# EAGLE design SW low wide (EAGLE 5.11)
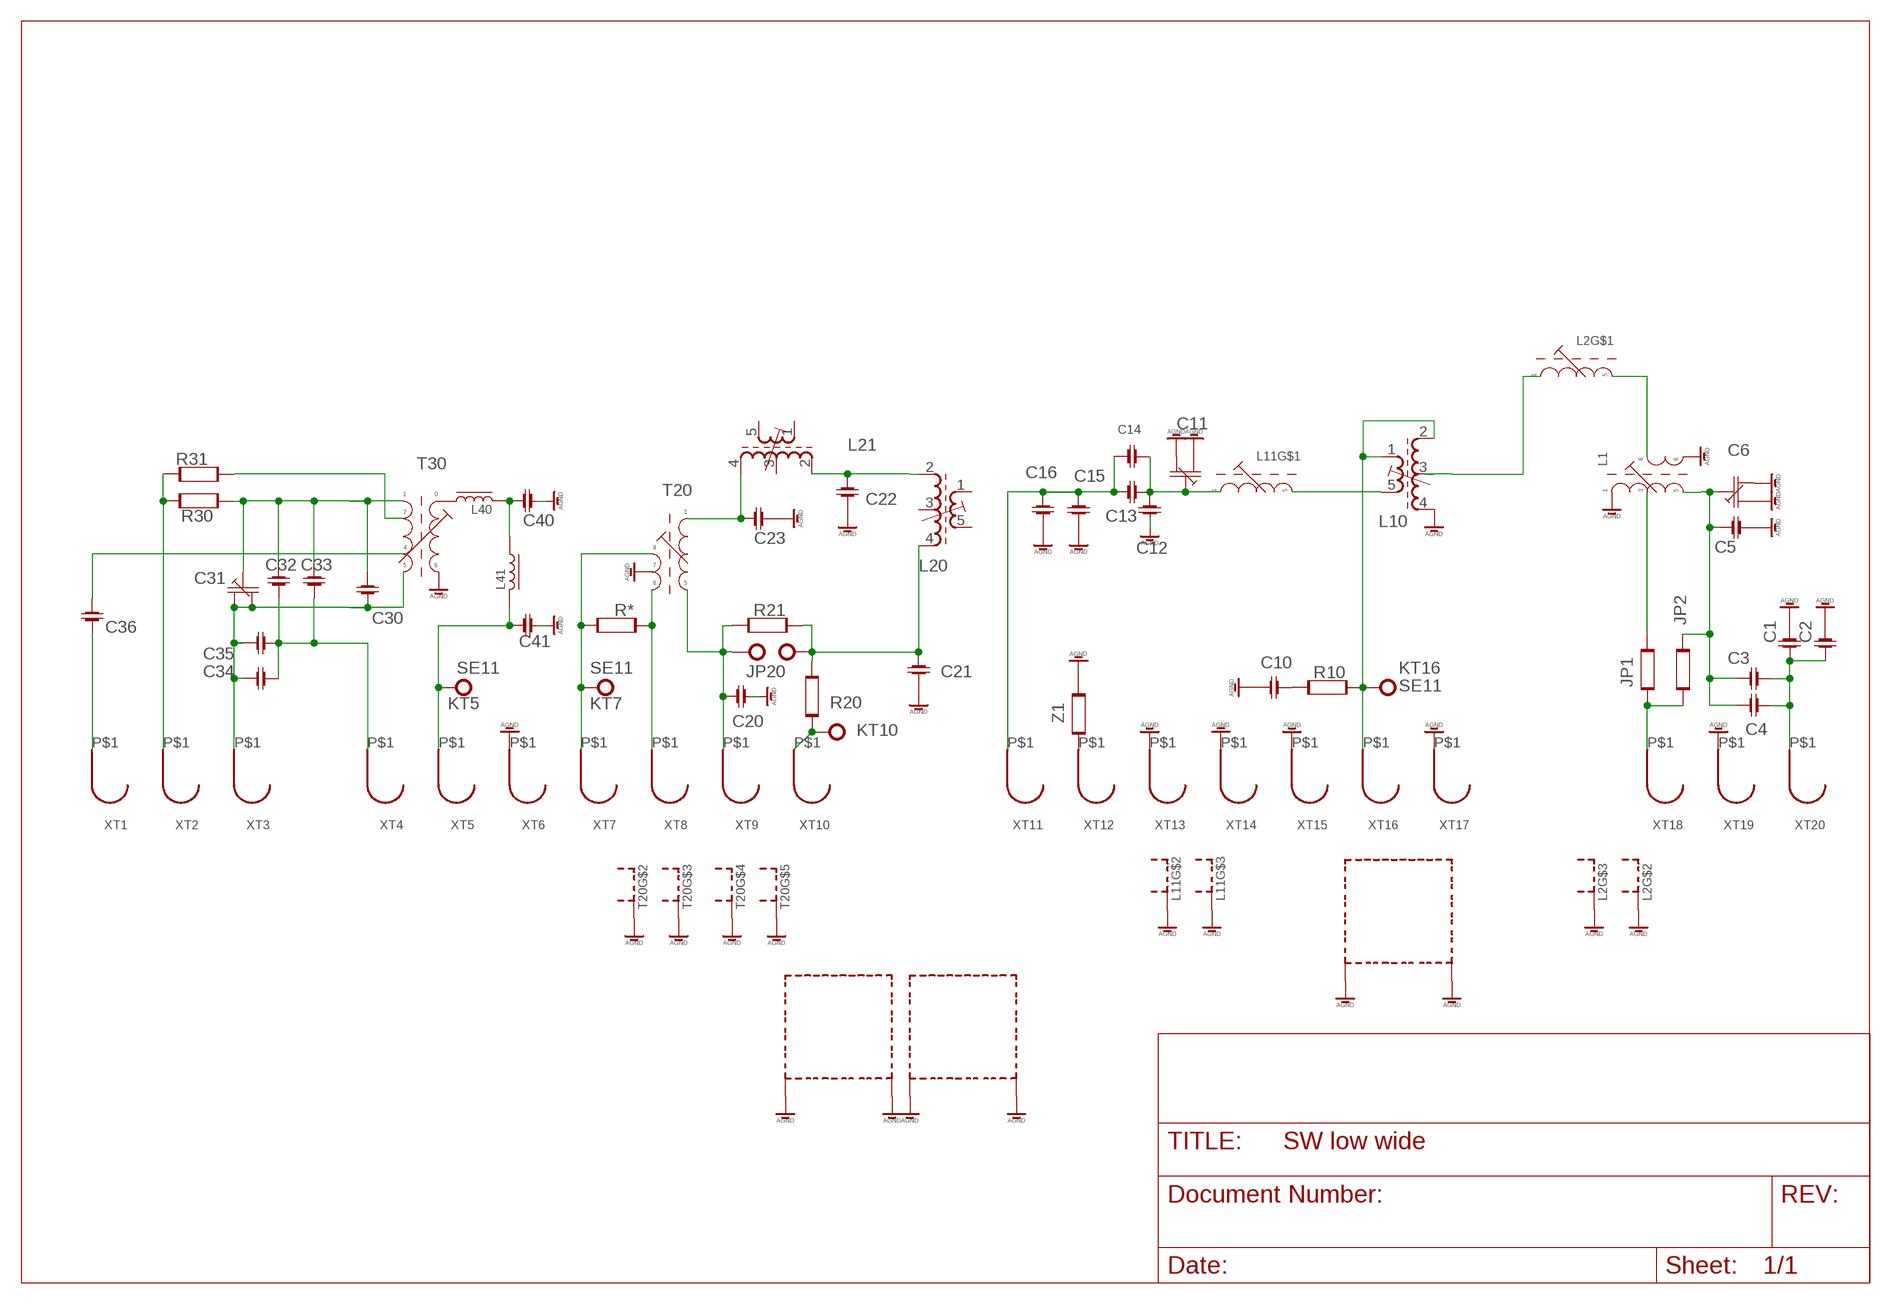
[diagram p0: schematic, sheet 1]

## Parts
C1  C-1206-0805  [RC-SMD-UNIV]
C2  C-1206-0805  [RC-SMD-UNIV]
C3  C-1206-0805  [RC-SMD-UNIV]
C4  C-1206-0805  [RC-SMD-UNIV]
C5  C-1206-0805  [RC-SMD-UNIV]
C6  C-TRIM-AM  [C-TRIM-ORIG]
C10  C-1206-0805  [RC-SMD-UNIV]
C11  C-TRIM-AM  [C-TRIM-ORIG]
C12  C-1206-0805  [RC-SMD-UNIV]
C13  C-1206-0805  [RC-SMD-UNIV]
C14  C-1206-0805  [RC-SMD-UNIV]
C15  C-1206-0805  [RC-SMD-UNIV]
C16  C-1206-0805  [RC-SMD-UNIV]
C20  C-1206-0805  [RC-SMD-UNIV]
C21  C-1206-0805  [RC-SMD-UNIV]
C22  C-1206-0805  [RC-SMD-UNIV]
C23  C-1206-0805  [RC-SMD-UNIV]
C30  C-1206-0805  [RC-SMD-UNIV]
C31  C-TRIM-AM  [C-TRIM-ORIG]
C32  C-1206-0805  [RC-SMD-UNIV]
C33  C-1206-0805  [RC-SMD-UNIV]
C34  C-1206-0805  [RC-SMD-UNIV]
C35  C-1206-0805  [RC-SMD-UNIV]
C36  C-1206-0805  [RC-SMD-UNIV]
C40  C-1206-0805  [RC-SMD-UNIV]
C41  C-1206-0805  [RC-SMD-UNIV]
JP1  R-1206-0805  [RC-SMD-UNIV]
JP2  R-1206-0805  [RC-SMD-UNIV]
JP20  SE11  [SE11]
KT1  SE11  [SE11]
KT5  SE11  [SE11]
KT7  SE11  [SE11]
KT10  SE11  [SE11]
KT16  SE11  [SE11]
L1  L-MOD-SW-IN-OPEN  [L-KW-LARGE]
L2  L-MOD-SW-GAP  [L-7-MM]
L10  71-5-24153  [71-5]
L11  L-MOD-SW-GAP  [L-7-MM]
L20  71-5-24153  [71-5]
L21  71-5-24153  [71-5]
L40  L-US0207/10  [0207/10]
L41  L-US0207/10  [0207/10]
R10  R-1206-0805  [RC-SMD-UNIV]
R20  R-1206-0805  [RC-SMD-UNIV]
R21  R-1206-0805  [RC-SMD-UNIV]
R30  R-1206-0805  [RC-SMD-UNIV]
R31  R-1206-0805  [RC-SMD-UNIV]
R*  R-1206-0805  [RC-SMD-UNIV]
T20  209-N-T90  [L-10-7-MM]
T30  L-MOD-OSC-SW  [L-KW-LARGE]
XT1  CONTACT-RF  [CONTACT-RF]
XT2  CONTACT-RF  [CONTACT-RF]
XT3  CONTACT-RF  [CONTACT-RF]
XT4  CONTACT-RF  [CONTACT-RF]
XT5  CONTACT-RF  [CONTACT-RF]
XT6  CONTACT-RF  [CONTACT-RF]
XT7  CONTACT-RF  [CONTACT-RF]
XT8  CONTACT-RF  [CONTACT-RF]
XT9  CONTACT-RF  [CONTACT-RF]
XT10  CONTACT-RF  [CONTACT-RF]
XT11  CONTACT-RF  [CONTACT-RF]
XT12  CONTACT-RF  [CONTACT-RF]
XT13  CONTACT-RF  [CONTACT-RF]
XT14  CONTACT-RF  [CONTACT-RF]
XT15  CONTACT-RF  [CONTACT-RF]
XT16  CONTACT-RF  [CONTACT-RF]
XT17  CONTACT-RF  [CONTACT-RF]
XT18  CONTACT-RF  [CONTACT-RF]
XT19  CONTACT-RF  [CONTACT-RF]
XT20  CONTACT-RF  [CONTACT-RF]
Z1  R-1206-0805  [RC-SMD-UNIV]

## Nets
AGND: C1.P$2 C2.P$2 C5.P$1 C6.P$6 C6.P$7 C10.P$2 C11.P$6 C11.P$7 C12.P$2 C15.P$1 C16.P$2 C20.P$2 C21.P$1 C22.P$1 C23.P$1 C40.P$1 C41.P$2 L1.P$2 L1.P$3 L2.P$6(S) L2.P$7(S) L10.4(E1) L10.S1 L10.S2 L11.P$6(S) L11.P$7(S) L20.S1 L20.S2 L21.S1 L21.S2 T20.2 T20.11(S) T20.12(S) T20.13(S) T20.14(S) T30.P$2 XT6.P$1 XT13.P$1 XT14.P$1 XT15.P$1 XT17.P$1 XT19.P$1 Z1.P$2
KT1: KT16.MP L10.1(A2) L10.2(A1) R10.P$2 XT16.P$1
N$1: C1.P$1 C2.P$1 C3.P$2 C4.P$2 XT20.P$1
N$2: JP1.P$2 JP2.P$2 XT18.P$1
N$3: C20.P$1 KT1.MP R21.P$1 T20.4 XT9.P$1
N$4: JP1.P$1 L1.P$5
N$5: R*.P$2 T20.3 XT8.P$1
N$7: C11.P$5 C12.P$1 C13.P$1 C14.P$2 L11.1
N$8: L1.P$6 L2.3
N$9: C21.P$2 JP20.MP L20.4(E1) R20.P$1 R21.P$2
N$10: XT12.P$1 Z1.P$1
N$11: KT10.MP R20.P$2 XT10.P$1
N$12: C13.P$2 C14.P$1 C15.P$2 C16.P$1 XT11.P$1
N$13: KT7.MP R*.P$1 T20.1 XT7.P$1
N$14: C23.P$2 L21.4(E1) T20.5
N$15: C22.P$2 L20.2(A1) L21.2(A1)
N$16: R30.P$2 R31.P$1 XT2.P$1
N$18: L40.1 T30.P$3
N$19: C3.P$1 C4.P$1 C5.P$2 C6.P$5 JP2.P$1 L1.P$1
N$20: C30.P$2 C31.P$6 C31.P$7 C34.P$2 C35.P$2 T30.P$6 XT3.P$1
N$21: C32.P$2 C33.P$2 C34.P$1 C35.P$1 XT4.P$1
N$22: C30.P$1 C31.P$5 C32.P$1 C33.P$1 R30.P$1 T30.P$5
N$23: C41.P$1 KT5.MP L41.2 XT5.P$1
N$24: C36.P$1 T30.P$4
N$25: C40.P$2 L40.2 L41.1
N$26: C36.P$2 XT1.P$1
N$28: R31.P$2 T30.P$1
N$30: C10.P$1 R10.P$1
N$32: L10.5(E2) L11.3
N$33: L2.1 L10.3(Z)
Unconnected: L20.1(A2) L20.3(Z) L20.5(E2) L21.1(A2) L21.3(Z) L21.5(E2)

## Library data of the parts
C1-C5 C10 C12-C16 C20-C23 C30 C32-C36 C40 C41 = OKEAH:C-1206-0805
C6 C11 C31 = OKEAH:C-TRIM-AM
JP1 JP2 R10 R20 R21 R30 R31 R* Z1 = OKEAH:R-1206-0805
JP20 KT1 KT5 KT7 KT10 KT16 = solpad:SE11: SOLDER PAD
L1 = OKEAH:L-MOD-SW-IN-OPEN
L2 L11 = OKEAH:L-MOD-SW-GAP
L10 L20 L21 = L NEOSID:71-5-: TRANSFORMER adjustable filter transformer with tap; OC_FARNELL: unknown; OC_NEWARK: unknown
L40 L41 = rcl:L-US: INDUCTOR, American symbol
T20 = OKEAH:209-N-T90
T30 = OKEAH:L-MOD-OSC-SW
XT1-XT20 = OKEAH:CONTACT-RF

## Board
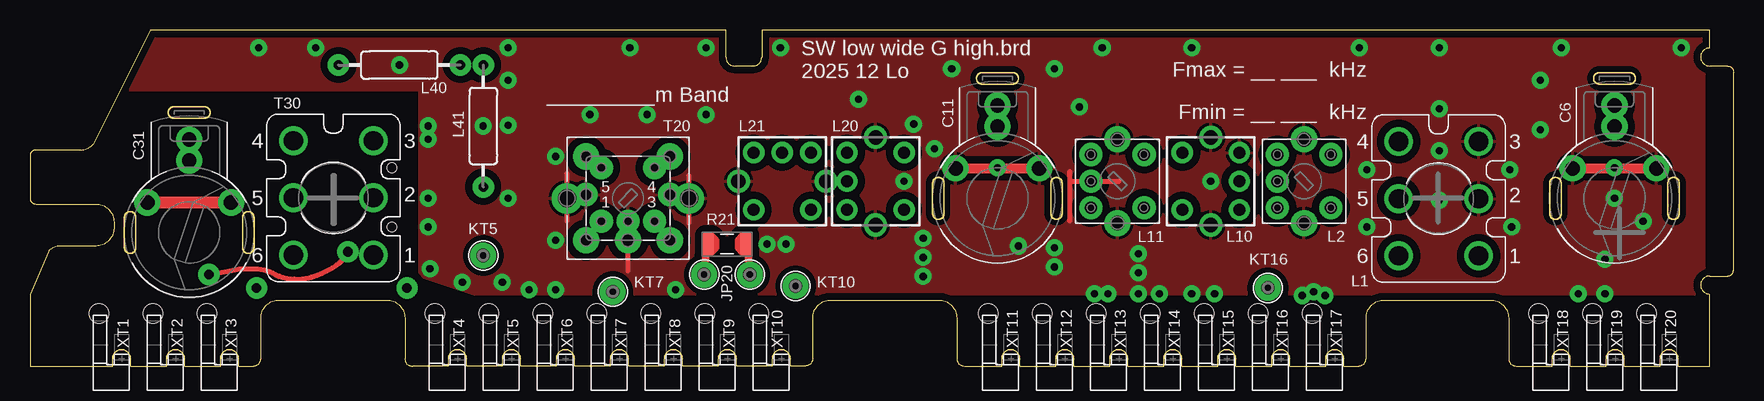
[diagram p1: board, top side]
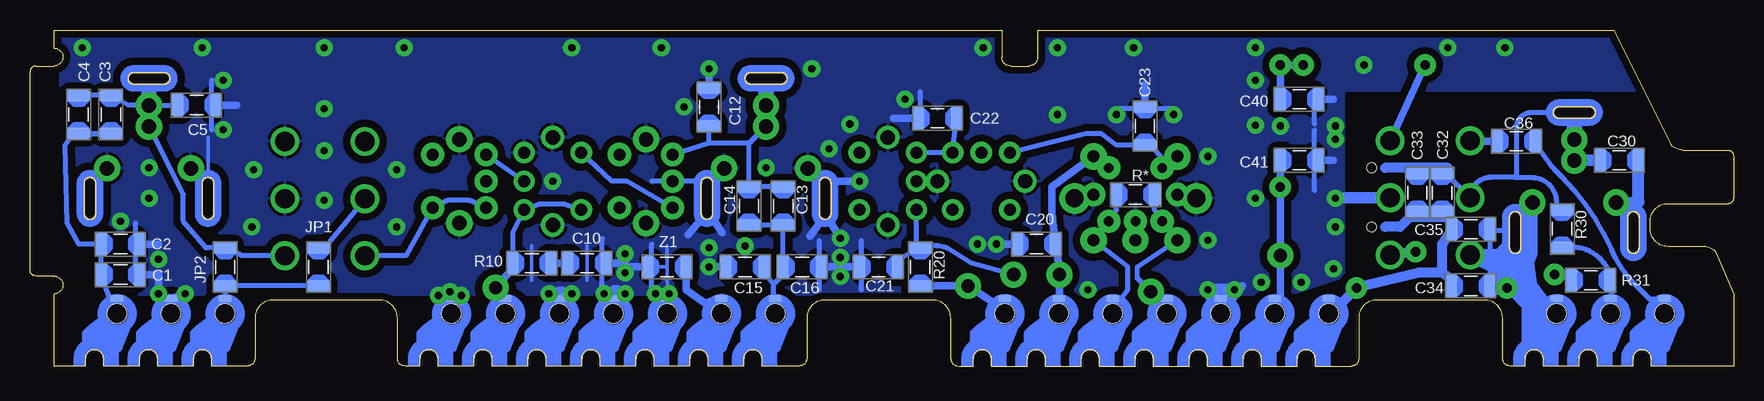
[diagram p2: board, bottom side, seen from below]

Size 142 x 28 mm. Coordinates in mm from the lower left corner, seen from the top.
Outline: 135 segments
Copper layers (1*16): Top 0.035mm / dielectric 1.5mm / Bottom 0.035mm
Design rules "default *": minimum track width 10mil, minimum drill 24mil, track to track 8mil, track to pad 8mil, pad to pad 8mil, via to via 8mil, smd to smd 8mil, copper to edge 8mil, drill to drill 8mil, minimum pad ring 10mil, minimum via ring 8mil, stop-mask expansion 4mil, vias tented up to drill 0mil, thermal gap 10mil
Holes 0.8 mm at 30.16,16.51 30.16,11.59
bRestrict: 3 lines

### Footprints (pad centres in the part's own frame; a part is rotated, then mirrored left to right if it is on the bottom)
RC-SMD-UNIV = smd 0.965 x 1.93: P$1 -1.587,0; P$2 1.587,0
C-TRIM-ORIG = drill 1.2 pad 2.184 round: P$4 7.739,0; P$5 5.992,0; P$6 2.5,3.493; P$7 2.5,-3.493
SE11 = drill 1.1 pad 2.159 round: MP 0,0
L-KW-LARGE = drill 1.6 round: P$1 0,0; P$2 0,4.763; P$3 0,9.525; P$4 -6.668,9.525; P$5 -6.668,4.763; P$6 -6.668,0
L-7-MM = drill 1 pad 1.93 round: 1 -2.223,-2.223; 2 0,-2.223; 3 2.223,-2.223; 4 2.223,2.223; 5 -2.223,2.223 | drill 1.2 pad 2.184 round: P$6 3.493,0; P$7 -3.493,0
71-5 = drill 1 pad 1.778 round: 1 2.381,-2.381; 2 2.381,2.381; 3 0,2.381; 4 -2.381,2.381; 5 -2.381,-2.381 | drill 1.2 pad 1.93 round: S1 -3.651,0; S2 3.651,0
0207/10 = drill 0.8 pad 1.778 round: 1 -5.08,0; 2 5.08,0
L-10-7-MM = drill 0.8 pad 1.93 round: 1 -2.223,-1.905; 2 0,-1.905; 3 2.223,-1.905; 4 2.223,2.54; 5 -2.223,2.54 | drill 1 pad 2.184 round: 6 -3.493,-3.493; 7 0,-3.493; 8 3.493,-3.493; 9 3.493,3.493; 10 -3.493,3.493 | drill 1.5 pad 2.54 round: 11 -5.08,0; 14 5.08,0 | drill 1 pad 1.93 round: 12 -3.493,0.318; 13 3.493,0.318
CONTACT-RF = smd 1.016 x 0.508 bottom: P$1 1,-5.625 | hole 1.6: 1,-4.375

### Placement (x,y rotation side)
C1  134.46,7.62 0 bottom
C2  134.46,10.16 0 bottom
C3  135.25,20.96 270 bottom
C4  137.95,20.96 270 bottom
C5  128.11,21.75 180 bottom
C6  132.08,13.97 90 top
C10  95.57,8.57 0 bottom
C11  80.65,13.97 90 top
C12  85.41,21.59 90 bottom
C13  79.22,13.34 270 bottom
C14  82.07,13.34 90 bottom
C15  82.39,8.26 0 bottom
C16  77.63,8.26 0 bottom
C20  58.1,10.16 180 bottom
C21  71.28,8.26 0 bottom
C22  66.36,20.64 0 bottom
C23  49.05,20 270 bottom
C30  9.53,17.15 0 bottom
C31  13.27,11.13 90 top
C32  24.29,14.45 270 bottom
C33  26.35,14.45 270 bottom
C34  21.91,6.67 0 bottom
C35  21.9,11.4 0 bottom
C36  18.1,18.73 0 bottom
C40  36.2,22.23 180 bottom
C41  36.2,17.15 0 bottom
JP1  117.95,8.26 270 bottom
JP2  125.73,8.26 270 bottom
JP20  60.01,7.62 0 top
KT1  56.2,7.62 0 top
KT5  37.78,9.21 0 top
KT7  48.58,6.19 0 top
KT10  63.82,6.67 0 top
KT16  103.19,6.51 0 top
L1  120.75,9.19 0 top
L2  106.2,15.4 270 top
L10  98.42,15.4 270 top
L11  90.65,15.4 270 top
L20  70.48,15.4 90 top
L21  62.71,15.4 0 top
L40  30.8,25.08 0 top
L41  37.78,20 270 top
R10  100.17,8.57 180 bottom
R20  67.79,8.26 270 bottom
R21  58.1,10.16 0 top
R30  14.29,11.43 270 bottom
R31  11.91,7.15 180 bottom
R*  49.85,14.29 180 bottom
T20  49.85,13.97 0 top
T30  28.62,9.25 0 top
XT1  6.75,0 180 top
XT2  11.25,0 180 top
XT3  15.75,0 180 top
XT4  34.75,0 180 top
XT5  39.25,0 180 top
XT6  43.75,0 180 top
XT7  48.25,0 180 top
XT8  52.75,0 180 top
XT9  57.25,0 180 top
XT10  61.75,0 180 top
XT11  80.88,0 180 top
XT12  85.38,0 180 top
XT13  89.88,0 180 top
XT14  94.38,0 180 top
XT15  98.88,0 180 top
XT16  103.38,0 180 top
XT17  107.88,0 180 top
XT18  126.75,0 180 top
XT19  131.25,0 180 top
XT20  135.75,0 180 top
Z1  88.9,8.26 180 bottom

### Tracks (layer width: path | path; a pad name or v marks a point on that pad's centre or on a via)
AGND  (via drill 0.6 pad 1.42)
  Top 0.406: 49.85,7.94 49.85,10.32 | 86.68,12.07 86.68,16.19 | 86.68,15.4 90.81,15.4 | 44.77,12.07 44.77,16.04 | 54.93,11.91 54.93,15.88
  Bottom 0.305: v107,6.19 v107.95,5.88 | v88.74,6.03 88.9,7.15 88.9,10 | 91.76,8.26 88.9,8.26 | 127.16,15.88 127.16,19.05 | 95.57,7.15 95.57,10 | 100.17,7.15 100.17,10
  Bottom 0.406: XT17.P$1 v107,6.19 | 34.92,20.16 34.92,22.39 | 34.92,14.61 34.92,16.83 | 34.92,17.47 34.92,19.69 | 90.17,6.04 90.17,10.16 | 126.84,19.69 126.84,23.82 | 133.19,7.78 133.19,11.91 | 51.28,21.43 49.05,21.43 46.67,21.43 | 67.79,20.64 67.79,22.86 | 72.71,6.35 72.71,10.48 | 76.2,6.35 76.2,10.48 | 86.36,15.4 90.17,15.4 | 94.3,6.51 94.3,10.64
  Bottom 0.61: 44.13,6.35 43.5,5.4 XT6.P$1 41.91,5.4 40.96,6.67 | C41.P$2 33.34,17.15 | C40.P$1 33.34,22.23 | Z1.P$2 91.76,8.26 91.92,8.26 | XT13.P$1 v88.74,6.03 | C20.P$2 61.12,10.16 | C21.P$1 74.77,8.26 C16.P$2 | C23.P$1 49.05,23.5 | C22.P$1 70.01,20.64 | 92.39,8.57 C10.P$2 | 131.29,10.16 C2.P$2 | C1.P$2 131.29,7.62 v131.29,6.03 | v129.06,6.03 XT19.P$1 | C5.P$1 124.78,21.75 | 75.25,11.91 v74.45,10.64 | 86.2,12.07 87.15,10.96 | 84.93,12.07 84.3,11.12 | 76.2,11.91 76.99,10.8 | v72.87,15.4 74.77,15.4 | C12.P$2 v85.41,24.77 | C15.P$1 v85.41,8.26
  Bottom 0.813: XT14.P$1 93.34,5.72 93.34,6.35 93.03,6.35 v92.39,6.03 | XT15.P$1 97.63,6.19 97.95,6.19 97.79,5.72 v96.84,6.03
  Bottom 1.016: T30.P$2 v33.18,13.97 | v41.59,6.35 v43.81,6.35
  other vias: 33.18,20 37.78,20 30.8,25.08 33.18,11.59 23.81,26.51 33.18,18.89 106.05,5.88 19.05,26.51 61.44,10.16 39.85,26.51 39.85,13.97 33.34,8.1 74.45,9.05 74.45,7.46 39.84,20.08 46.67,20.96 123.51,11.59 98.42,15.4 39.37,6.99 94.14,6.03 98.74,6.03 39.85,23.81 117.47,17.94 36.04,6.99 75.41,18.1 85.41,9.84 43.81,17.46 51.43,20.96 43.81,10.48 73.66,20.16 69.06,22.23 56.36,20.96 62.55,26.51 76.83,24.77 117.47,21.43 89.85,6.03 50.01,26.51 56.36,26.51 87.47,21.59 111.44,16.35 117.47,13.81 132.08,13.97 134.46,12.07 80.64,16.51 125.89,19.69 132.08,16.51 131.29,8.89 125.89,23.81 127.63,26.51 137.64,26.51 110.81,26.51 123.35,16.35 96.84,26.51 117.48,26.51 111.44,11.59 89.38,26.51 82.39,10 63.02,10.16 92.39,7.78 92.39,9.37 53.82,6.35
  pour Top (isolate 0.61): 37,6 32.5,7.5 32.5,23 7.5,23 10,28 58,28 58,25 61,25 61,28 139.5,28 139.5,6
  pour Bottom (isolate 0.61): 10,28 139.5,28 139.5,6 37,6 32.5,7.5 32.5,23 7.5,23
KT1
  Bottom 0.406: XT16.P$1 102.39,5.63 | R10.P$2 101.76,11.12 L10.2 99.54,13.5 97.47,13.5 L10.1
  Bottom 0.61: XT16.P$1 103.03,5.56 KT16.MP 101.92,7.94 R10.P$2
N$1
  Bottom 0.406: XT20.P$1 135.25,5.4 C1.P$1 C2.P$1 137.95,10.16 138.91,11.91 139.06,18.42 138.43,19.37 C3.P$2 C4.P$2
N$2
  Bottom 0.406: JP1.P$2 JP2.P$2 125.73,5.72 XT18.P$1
N$3
  Top 0.61: KT1.MP 56.36,9.53 R21.P$1
  Bottom 0.61: XT9.P$1 56.2,5.88 KT1.MP 56.36,9.53 R21.P$1 56.83,12.7 56.83,14.92 53.34,17.46 T20.4
N$4
  Bottom 0.406: L1.P$5 117.32,10 JP1.P$1
N$5
  Bottom 0.406: XT8.P$1 51.12,5.56 50.48,6.35 50.48,8.26 53.34,10.48 T20.3 51.44,13.02 R*.P$2
N$7
  Bottom 0.406: 85.41,18.58 L11.1 | 85.41,18.58 C12.P$1 | 82.07,18.58 C14.P$2 C13.P$1 | 82.07,18.58 C11.P$5 82.07,18.58 | 82.07,18.58 85.41,18.58
N$8
  Bottom 0.406: L1.P$6 110.65,9.21 108.43,13.18 107.16,13.81 105.41,13.81 L2.3
N$9
  Top 0.61: R21.P$2 59.53,9.53 59.85,9.53 JP20.MP
  Bottom 0.406: L20.4 68.1,10 68.42,10 | R20.P$1 68.42,10 | 67.47,10 66.36,10 65.56,9.84 63.5,8.57 JP20.MP | C21.P$2 69.53,8.89 68.42,9.53 68.42,10
  Bottom 0.61: 67.47,10 R20.P$1
N$10
  Bottom 0.61: XT12.P$1 84.3,5.63 84.3,5.72 85.25,5.4 85.72,5.24 87.31,6.35 Z1.P$1
N$11
  Bottom 0.61: XT10.P$1 61.59,5.24 KT10.MP R20.P$2
N$12
  Bottom 0.406: XT11.P$1 80.01,5.72 80.01,6.83 | 80.01,6.83 80.64,7.62 C15.P$2 | 80.01,6.83 79.22,7.62 C16.P$1 C13.P$2 C14.P$1
N$13
  Bottom 0.406: XT7.P$1 KT7.MP 49.69,7.31 49.69,8.26 46.35,10.48 T20.1 48.26,13.02 R*.P$1
N$14
  Bottom 0.406: T20.5 47.62,17.31 48.42,18.26 C23.P$2 51.44,18.42 52.7,19.37 53.98,19.37 L21.4
N$15
  Bottom 0.406: L20.2 L21.2 C22.P$2
N$16
  Bottom 0.406: 10.16,6.19 XT2.P$1 | 10.16,6.19 arc-37 10.48,8.1 arc-52 12.86,9.84 arc-21 R30.P$2 | R31.P$1 10.16,7.15 10.16,6.19
N$17
  Bottom 0.813: 23.81,16.35 23.81,16.51 29.05,16.51
N$18
  Bottom 0.61: T30.P$3 L40.1
N$19
  Bottom 0.406: L1.P$1 124.3,9.21 JP2.P$1 127.32,9.84 129.22,12.07 129.22,14.29 C6.P$5 132.08,21.75 | 132.08,21.75 C5.P$2 | 132.08,21.75 133.83,21.75 | 133.83,21.75 C3.P$1 C4.P$1 | 132.08,21.75 133.83,21.75
N$20
  Top 1.016: C31.P$7 C31.P$6
  Bottom 0.406: 15.88,4.77 16.51,4.77 | 19.84,9.22 19.84,9.37 19.05,10.16 19.05,11.27 20.18,11.27 C35.P$2 C34.P$2
  Bottom 0.61: XT3.P$1 15.56,5.4 15.88,4.77
  Bottom 1.016: C30.P$2 7.94,13.65 C31.P$6 | 16.51,4.77 15.88,5.4 16.83,6.67 16.82,6.51 17.12,8.57 | 17.12,8.57 16.83,9.37 16.83,13.63 C31.P$7 | T30.P$6 19.84,9.22 19.37,9.21 19.37,8.57 17.12,8.57
  Bottom 1.27: 16.82,6.51 20.16,6.51
N$21  (via drill 0.8 pad 1.78)
  Bottom 0.406: C34.P$1 23.65,7.31 | XT4.P$1 32.7,5.24 v31.43,6.51
  Bottom 0.61: C35.P$1 23.81,12.86 C32.P$2 C33.P$2
  Bottom 0.813: C35.P$1 24.29,10.16 24.29,7.78 | 23.65,7.31 24.29,7.78 | 32.7,5.24 v31.43,6.51 26.19,7.78 24.29,7.78 | C32.P$2 24.29,12.7 23.97,12.39 26.99,12.39 | 26.99,12.39 | 26.99,12.39 27.78,11.59 29.05,11.59
N$22
  Bottom 0.406: R30.P$1 14.76,13.18 14.76,13.66 arc-90 16.83,15.72 18.26,15.72 | 18.26,15.72 20.25,15.72 arc-90 T30.P$5 23.89,15.94 arc-45 24.11,16.04 C32.P$1 | C31.P$5 13.27,20.17 arc-45 13.34,20.32 14.79,20.32 arc45 15.02,20.42 15.24,20.64 15.24,20.83 arc-45 15.33,21.05 15.4,21.12 16.83,21.12 arc-90 18.1,19.85 18.1,15.88 arc90 18.26,15.72
  Bottom 0.61: C32.P$1 24.77,16.19 25.72,16.19 C33.P$1
  Bottom 1.016: C30.P$1 C31.P$5
N$23
  Bottom 0.61: L41.2 C41.P$1 KT5.MP | KT5.MP 37.78,5.72 XT5.P$1 | KT5.MP 37.78,6.35
N$24
  Bottom 0.61: C36.P$1 20.95,18.74 T30.P$4
N$25
  Bottom 0.61: C40.P$2 L41.1 L40.2
N$26
  Bottom 0.406: XT1.P$1 6.35,5.56 6.85,5.56 arc45 7.08,5.65 8.1,6.67 arc21 10.16,9.69 arc-21 14.29,15.72 arc13 16.19,18.1 arc12 C36.P$2
N$27  (via drill 0.8 pad 1.78)
  Bottom 0.406: v18.89,6.51 19.37,6.51 19.37,6.99
  Bottom 1.016: 18.41,6.35 19.21,8.42 21.91,9.21 19.68,8.1 19.37,6.99 19.37,8.89 18.73,7.62 17.14,7.62 17.14,5.08 | 18.41,6.35 17.14,6.35 16.51,3.81 17.14,2.86 17.14,5.08 | 17.14,5.08 18.41,6.35
N$28  (via drill 0.8 pad 1.78)
  Top 0.406: v14.92,7.62 17.46,8.1 18.73,8.1 arc-30 20.48,7.62 arc36 23.02,7.31 arc25 25.56,8.42 arc27 v26.51,9.53
  Bottom 0.813: v14.92,7.62 13.49,7.62 R31.P$2 | v26.51,9.53 T30.P$1
N$30
  Bottom 0.61: R10.P$1 C10.P$1
N$32
  Bottom 0.406: L11.3 92.23,15.4 93.5,15.4 L10.5
N$33
  Bottom 0.406: L10.3 L2.1

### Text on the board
tPlace: SW low wide G high.brd | Fmax = __ ___ kHz | 2025 12 Lo | _________m Band | Fmin = __ ___ kHz
tDocu: ANT Modul | grid placement = 0.125mm | grid placement = 0.125mm | grid SMD = 0.3175mm | grid SMD = 0.3175mm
